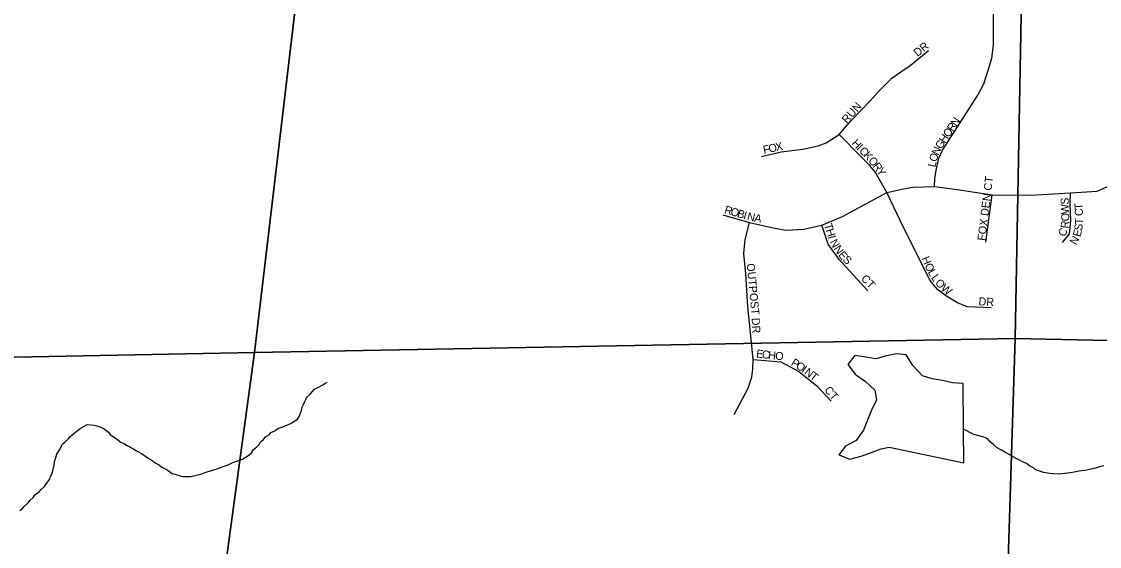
# Model space of a CAD drawing. Extents: x 0 to 34, y -2.3 to 22.
# Drawn here: x 3.123 to 4.399, y 15.2 to 15.821 of the extents above; entities that cross this region are included whole.
import ezdxf

# ---------------------------------------------------------------- set-up
doc = ezdxf.new("R2010")
doc.units = 0
for name, color, linetype in [('GM_X_Minor_River', 7, 'Continuous'), ('GM_X_Section', 7, 'Continuous'), ('GM_X_Township_Subdivision', 7, 'Continuous'), ('GM_X_Township_Subdivision_Text', 7, 'Continuous')]:
    doc.layers.add(name, color=color, linetype=linetype)

msp = doc.modelspace()

# ---------------------------------------------------------------- linework, layer by layer
at = {"layer": 'GM_X_Minor_River'}
for p, q in [((4.1094, 15.4259), (4.1011, 15.4154)), ((4.1223, 15.424), (4.1094, 15.4259)), ((4.1344, 15.4221), (4.1223, 15.424)), ((4.147, 15.4255), (4.1344, 15.4221)), ((4.1585, 15.4282), (4.147, 15.4255)), ((4.1702, 15.4267), (4.1585, 15.4282)), ((4.1782, 15.4143), (4.1702, 15.4267)), ((4.1011, 15.4154), (4.1099, 15.4038)), ((4.1893, 15.4022), (4.1782, 15.4143)), ((4.1099, 15.4038), (4.1218, 15.3954)), ((4.1218, 15.3954), (4.1329, 15.3852)), ((4.201, 15.3985), (4.1893, 15.4022)), ((4.2131, 15.3966), (4.201, 15.3985)), ((4.2251, 15.3939), (4.2131, 15.3966)), ((3.465, 15.3803), (3.4701, 15.3862)), ((3.4701, 15.3862), (3.4739, 15.3884)), ((3.4739, 15.3884), (3.4797, 15.3912)), ((3.4797, 15.3912), (3.4824, 15.393)), ((3.4824, 15.393), (3.4851, 15.3945)), ((4.1329, 15.3852), (4.1349, 15.3738)), ((4.2376, 15.3928), (4.2251, 15.3939)), ((4.238, 15.3391), (4.2376, 15.3928)), ((3.457, 15.368), (3.4582, 15.371)), ((3.4582, 15.371), (3.4598, 15.374)), ((3.4598, 15.374), (3.4611, 15.3766)), ((3.4611, 15.3766), (3.465, 15.3803)), ((4.1349, 15.3738), (4.1292, 15.3614)), ((3.4525, 15.3559), (3.4545, 15.3608)), ((3.4545, 15.3608), (3.4554, 15.365)), ((3.4554, 15.365), (3.457, 15.368)), ((4.1292, 15.3614), (4.1243, 15.3497)), ((3.1982, 15.343), (3.2009, 15.3445)), ((3.2009, 15.3445), (3.2092, 15.3438)), ((3.2092, 15.3438), (3.2126, 15.343)), ((3.4354, 15.3428), (3.4381, 15.3442)), ((3.4381, 15.3442), (3.4419, 15.3456)), ((3.4419, 15.3456), (3.4446, 15.3474)), ((3.4446, 15.3474), (3.45, 15.3507)), ((3.45, 15.3507), (3.4516, 15.3533)), ((3.4516, 15.3533), (3.4525, 15.3559)), ((4.1243, 15.3497), (4.1198, 15.3377)), ((3.1803, 15.3299), (3.1834, 15.3321)), ((3.1834, 15.3321), (3.19, 15.3376)), ((3.19, 15.3376), (3.1928, 15.3398)), ((3.1928, 15.3398), (3.1982, 15.343)), ((3.2126, 15.343), (3.216, 15.3417)), ((3.216, 15.3417), (3.2201, 15.3401)), ((3.2201, 15.3401), (3.2261, 15.3353)), ((3.2261, 15.3353), (3.2283, 15.3326)), ((3.2283, 15.3326), (3.2369, 15.3267)), ((3.4122, 15.3298), (3.4164, 15.3323)), ((3.4164, 15.3323), (3.4184, 15.3349)), ((3.4184, 15.3349), (3.4238, 15.3374)), ((3.4238, 15.3374), (3.4265, 15.3396)), ((3.4265, 15.3396), (3.4327, 15.3417)), ((3.4327, 15.3417), (3.4354, 15.3428)), ((4.1198, 15.3377), (4.111, 15.3254)), ((4.2383, 15.2992), (4.238, 15.3391)), ((4.2493, 15.3329), (4.238, 15.3391)), ((4.2519, 15.3321), (4.2493, 15.3329)), ((4.261, 15.3299), (4.2519, 15.3321)), ((3.1681, 15.3143), (3.1717, 15.321)), ((3.1717, 15.321), (3.1748, 15.324)), ((3.1748, 15.324), (3.1787, 15.3269)), ((3.1787, 15.3269), (3.1803, 15.3299)), ((3.2369, 15.3267), (3.2402, 15.3239)), ((3.2402, 15.3239), (3.2451, 15.3215)), ((3.2451, 15.3215), (3.2484, 15.3195)), ((3.2484, 15.3195), (3.2552, 15.3162)), ((3.4016, 15.318), (3.4047, 15.3209)), ((3.4047, 15.3209), (3.4063, 15.3239)), ((3.4063, 15.3239), (3.4094, 15.3261)), ((3.4094, 15.3261), (3.4122, 15.3298)), ((4.0983, 15.3189), (4.0904, 15.3085)), ((4.111, 15.3254), (4.0983, 15.3189)), ((4.2647, 15.3283), (4.261, 15.3299)), ((4.2673, 15.3267), (4.2647, 15.3283)), ((4.2695, 15.324), (4.2673, 15.3267)), ((4.274, 15.3204), (4.2695, 15.324)), ((4.2777, 15.3169), (4.274, 15.3204)), ((3.1624, 15.3004), (3.1644, 15.3064)), ((3.1644, 15.3064), (3.1653, 15.3094)), ((3.1653, 15.3094), (3.1681, 15.3143)), ((3.2552, 15.3162), (3.2593, 15.3131)), ((3.2593, 15.3131), (3.266, 15.3098)), ((3.266, 15.3098), (3.2705, 15.3067)), ((3.2705, 15.3067), (3.2731, 15.3047)), ((3.3848, 15.3036), (3.3891, 15.3062)), ((3.3891, 15.3062), (3.3922, 15.308)), ((3.3922, 15.308), (3.3953, 15.3109)), ((3.3953, 15.3109), (3.3977, 15.315)), ((3.3977, 15.315), (3.4016, 15.318)), ((4.0904, 15.3085), (4.1036, 15.3036)), ((4.1036, 15.3036), (4.117, 15.307)), ((4.117, 15.307), (4.1266, 15.3105)), ((4.1266, 15.3105), (4.1404, 15.3158)), ((4.1404, 15.3158), (4.15, 15.3178)), ((4.15, 15.3178), (4.2383, 15.2992)), ((4.2822, 15.3145), (4.2777, 15.3169)), ((4.2867, 15.3117), (4.2822, 15.3145)), ((4.2919, 15.3089), (4.2867, 15.3117)), ((4.2945, 15.3073), (4.2919, 15.3089)), ((4.3043, 15.3024), (4.2945, 15.3073)), ((3.1602, 15.2898), (3.1619, 15.2962)), ((3.1619, 15.2962), (3.1624, 15.3004)), ((3.2731, 15.3047), (3.2776, 15.3023)), ((3.2776, 15.3023), (3.2813, 15.2991)), ((3.2813, 15.2991), (3.2865, 15.2963)), ((3.2865, 15.2963), (3.2895, 15.2939)), ((3.2895, 15.2939), (3.2955, 15.2907)), ((3.3537, 15.2917), (3.3621, 15.2948)), ((3.3621, 15.2948), (3.3679, 15.2969)), ((3.3679, 15.2969), (3.3725, 15.2991)), ((3.3725, 15.2991), (3.3764, 15.3005)), ((3.3764, 15.3005), (3.3848, 15.3036)), ((4.3069, 15.3008), (4.3043, 15.3024)), ((4.3125, 15.2984), (4.3069, 15.3008)), ((4.3159, 15.2956), (4.3125, 15.2984)), ((4.3207, 15.2932), (4.3159, 15.2956)), ((4.3233, 15.2908), (4.3207, 15.2932)), ((4.3941, 15.2929), (4.3849, 15.2909)), ((4.3987, 15.2943), (4.3941, 15.2929)), ((4.404, 15.2956), (4.3987, 15.2943)), ((3.1568, 15.2797), (3.1577, 15.2831)), ((3.1577, 15.2831), (3.1593, 15.2857)), ((3.1593, 15.2857), (3.1602, 15.2898)), ((3.2955, 15.2907), (3.3015, 15.2864)), ((3.3015, 15.2864), (3.3049, 15.2855)), ((3.3049, 15.2855), (3.3124, 15.2834)), ((3.3124, 15.2834), (3.315, 15.2829)), ((3.315, 15.2829), (3.3207, 15.2828)), ((3.3207, 15.2828), (3.3238, 15.283)), ((3.3238, 15.283), (3.3356, 15.2857)), ((3.3356, 15.2857), (3.3395, 15.2871)), ((3.3395, 15.2871), (3.3506, 15.2906)), ((3.3506, 15.2906), (3.3537, 15.2917)), ((4.3293, 15.2887), (4.3233, 15.2908)), ((4.3327, 15.2875), (4.3293, 15.2887)), ((4.3399, 15.2865), (4.3327, 15.2875)), ((4.3437, 15.286), (4.3399, 15.2865)), ((4.3517, 15.2858), (4.3437, 15.286)), ((4.3544, 15.2861), (4.3517, 15.2858)), ((4.3647, 15.2873), (4.3544, 15.2861)), ((4.3689, 15.2879), (4.3647, 15.2873)), ((4.375, 15.2893), (4.3689, 15.2879)), ((4.3815, 15.2902), (4.375, 15.2893)), ((4.3849, 15.2909), (4.3815, 15.2902)), ((3.1438, 15.2645), (3.1466, 15.2674)), ((3.1466, 15.2674), (3.1505, 15.2711)), ((3.1505, 15.2711), (3.1529, 15.2745)), ((3.1529, 15.2745), (3.1568, 15.2797)), ((3.1313, 15.2516), (3.1333, 15.2545)), ((3.1333, 15.2545), (3.1372, 15.2582)), ((3.1372, 15.2582), (3.1396, 15.2616)), ((3.1396, 15.2616), (3.1438, 15.2645)), ((3.1212, 15.2427), (3.1246, 15.2449)), ((3.1246, 15.2449), (3.1266, 15.2475)), ((3.1266, 15.2475), (3.1313, 15.2516))]:
    msp.add_line(p, q, dxfattribs=at)
at = {"layer": 'GM_X_Section'}
for p, q in [((3.5141, 16.4057), (3.3991, 15.4295)), ((3.3991, 15.4295), (3.5141, 16.4057)), ((4.317, 16.3953), (4.2992, 15.4463)), ((4.2992, 15.4463), (4.317, 16.3953)), ((4.2992, 15.4463), (3.3991, 15.4295)), ((3.3991, 15.4295), (4.2992, 15.4463)), ((4.268, 14.4527), (4.2992, 15.4463)), ((4.2992, 15.4463), (4.268, 14.4527)), ((5.3014, 15.4224), (4.2992, 15.4463)), ((4.2992, 15.4463), (5.3014, 15.4224)), ((3.3991, 15.4295), (2.4872, 15.4126)), ((2.4872, 15.4126), (3.3991, 15.4295)), ((3.2685, 14.4772), (3.3991, 15.4295)), ((3.3991, 15.4295), (3.2685, 14.4772))]:
    msp.add_line(p, q, dxfattribs=at)
at = {"layer": 'GM_X_Township_Subdivision'}
for p, q in [((4.2733, 15.8147), (4.2733, 15.8348)), ((4.2733, 15.7932), (4.2733, 15.8147)), ((4.2714, 15.7779), (4.2733, 15.7932)), ((4.1749, 15.7692), (4.1967, 15.7869)), ((4.2677, 15.7649), (4.2714, 15.7779)), ((4.1639, 15.7617), (4.1749, 15.7692)), ((4.2621, 15.7474), (4.2677, 15.7649)), ((4.1453, 15.7463), (4.1532, 15.7541)), ((4.1532, 15.7541), (4.1639, 15.7617)), ((4.1372, 15.7385), (4.1453, 15.7463)), ((4.2551, 15.734), (4.2621, 15.7474)), ((4.1053, 15.7045), (4.1279, 15.7277)), ((4.1279, 15.7277), (4.1372, 15.7385)), ((4.2132, 15.669), (4.2551, 15.734)), ((4.0907, 15.6876), (4.1053, 15.7045)), ((4.0658, 15.6741), (4.0756, 15.6778)), ((4.0756, 15.6778), (4.0907, 15.6876)), ((4.1174, 15.6606), (4.0907, 15.6876)), ((3.9991, 15.6617), (4.0222, 15.667)), ((4.0222, 15.667), (4.0478, 15.6702)), ((4.0478, 15.6702), (4.0658, 15.6741)), ((4.2089, 15.6594), (4.2132, 15.669)), ((4.127, 15.6508), (4.1174, 15.6606)), ((4.1337, 15.6424), (4.127, 15.6508)), ((4.2058, 15.6452), (4.2089, 15.6594)), ((4.1395, 15.6328), (4.1337, 15.6424)), ((4.204, 15.6352), (4.2058, 15.6452)), ((4.3961, 15.6205), (4.4346, 15.6378)), ((4.1471, 15.6188), (4.1395, 15.6328)), ((4.1671, 15.6232), (4.1782, 15.6252)), ((4.1782, 15.6252), (4.2035, 15.626)), ((4.2035, 15.626), (4.204, 15.6352)), ((4.2035, 15.626), (4.2303, 15.6223)), ((4.0947, 15.5906), (4.1471, 15.6188)), ((4.1471, 15.6188), (4.1671, 15.6232)), ((4.1633, 15.5852), (4.1471, 15.6188)), ((4.2303, 15.6223), (4.2718, 15.6162)), ((4.2643, 15.5602), (4.2718, 15.6162)), ((4.2718, 15.6162), (4.3175, 15.6158)), ((4.3175, 15.6158), (4.3644, 15.6184)), ((4.3641, 15.6062), (4.3644, 15.6184)), ((4.3644, 15.6184), (4.3961, 15.6205)), ((4.3651, 15.5853), (4.3641, 15.6062)), ((3.9531, 15.5924), (3.9849, 15.5836)), ((4.0704, 15.5802), (4.0947, 15.5906)), ((3.9795, 15.5634), (3.9849, 15.5836)), ((3.9849, 15.5836), (4.0129, 15.577)), ((4.0129, 15.577), (4.0283, 15.5744)), ((4.0283, 15.5744), (4.0489, 15.5756)), ((4.0489, 15.5756), (4.0704, 15.5802)), ((4.078, 15.5579), (4.0704, 15.5802)), ((4.1897, 15.5317), (4.1633, 15.5852)), ((4.3634, 15.5701), (4.3651, 15.5853)), ((3.9781, 15.5468), (3.9795, 15.5634)), ((4.3552, 15.5597), (4.3634, 15.5701)), ((4.0907, 15.5396), (4.078, 15.5579)), ((3.9804, 15.5227), (3.9781, 15.5468)), ((4.1248, 15.5027), (4.0907, 15.5396)), ((3.9827, 15.4835), (3.9804, 15.5227)), ((4.1987, 15.5149), (4.1897, 15.5317)), ((4.2072, 15.5042), (4.1987, 15.5149)), ((4.2182, 15.4957), (4.2072, 15.5042)), ((4.231, 15.4882), (4.2182, 15.4957)), ((4.2423, 15.4838), (4.231, 15.4882)), ((3.9859, 15.4533), (3.9827, 15.4835)), ((4.2707, 15.4824), (4.2423, 15.4838)), ((3.9891, 15.4214), (3.9859, 15.4533)), ((3.9888, 15.4104), (3.9891, 15.4214)), ((3.9891, 15.4214), (4.022, 15.4185)), ((3.9874, 15.4005), (3.9888, 15.4104)), ((4.022, 15.4185), (4.0433, 15.4073)), ((3.9833, 15.3874), (3.9874, 15.4005)), ((4.0433, 15.4073), (4.0642, 15.3907)), ((3.9665, 15.3564), (3.9833, 15.3874)), ((4.0642, 15.3907), (4.0812, 15.3721))]:
    msp.add_line(p, q, dxfattribs=at)

# ---------------------------------------------------------------- texts
at = {"layer": 'GM_X_Township_Subdivision_Text'}
for s, rotation, p in [('DR', 38.1565, (4.1835, 15.7792)), ('RUN', 48.1233, (4.1, 15.6999)), ('R', 56.0018, (4.2254, 15.6902)), ('N', 56.0018, (4.2296, 15.6964)), ('H', 56.0144, (4.216, 15.6764)), ('O', 56.0053, (4.2207, 15.6833)), ('F', 11.8324, (4.0018, 15.6646)), ('O', 11.8318, (4.0083, 15.666)), ('X', 12.5173, (4.0166, 15.6677)), ('H', 313.7673, (4.1051, 15.6766)), ('I', 313.7483, (4.1108, 15.6706)), ('G', 57.3587, (4.2116, 15.6694)), ('C', 313.7663, (4.1137, 15.6676)), ('K', 313.7673, (4.1189, 15.6621)), ('O', 73.7634, (4.206, 15.6545)), ('N', 65.0088, (4.2082, 15.6622)), ('O', 311.447, (4.1246, 15.6562)), ('R', 306.2943, (4.13, 15.6501)), ('L', 76.9644, (4.2046, 15.6482)), ('Y', 303.4279, (4.1344, 15.6442)), ('FOX DEN CT', 82.9618, (4.2637, 15.5614)), ('S', 88.0326, (4.3623, 15.6043)), ('R', 343.5025, (3.9543, 15.5945)), ('O', 343.4926, (3.9615, 15.5924)), ('B', 343.4977, (3.9695, 15.5901)), ('W', 93.7649, (4.363, 15.5937)), ('T', 92.8017, (4.379, 15.5988)), ('C', 94.1356, (4.3795, 15.5914)), ('I', 343.5117, (3.9767, 15.5879)), ('N', 346.7533, (3.9813, 15.5866)), ('A', 349.9328, (3.9899, 15.5846)), ('O', 91.0971, (4.3632, 15.5849)), ('T', 87.0526, (4.3793, 15.5809)), ('T', 286.7176, (4.073, 15.5808)), ('H', 286.7217, (4.0749, 15.5745)), ('C', 62.2347, (4.3575, 15.5658)), ('R', 82.6307, (4.3621, 15.576)), ('E', 75.2954, (4.3762, 15.5658)), ('S', 80.9052, (4.3781, 15.5732)), ('I', 286.7165, (4.0773, 15.5665)), ('N', 298.6302, (4.0794, 15.5605)), ('N', 60.6285, (4.3712, 15.5561)), ('N', 304.6385, (4.0839, 15.5523)), ('E', 308.8792, (4.0891, 15.5448)), ('S', 316.7636, (4.0943, 15.5386)), ('H', 292.7014, (4.188, 15.541)), ('O', 296.6582, (4.1915, 15.5326)), ('OUTPOST', 275.4414, (3.9814, 15.5346)), ('L', 298.8858, (4.1954, 15.5248)), ('L', 303.7429, (4.1991, 15.5182)), ('CT', 312.7085, (4.116, 15.5165)), ('O', 311.5519, (4.2037, 15.5116)), ('W', 321.0905, (4.2104, 15.5042)), ('DR', 356.9889, (4.2556, 15.4855)), ('DR', 273.011, (3.9873, 15.4704)), ('E', 353.7171, (3.9923, 15.4238)), ('C', 353.7094, (3.999, 15.423)), ('H', 353.7116, (4.0064, 15.4222)), ('O', 354.4425, (4.0148, 15.4213)), ('P', 328.2386, (4.0331, 15.4152)), ('O', 326.5494, (4.0387, 15.4117)), ('I', 323.2656, (4.0455, 15.4072)), ('N', 322.5793, (4.0488, 15.4047)), ('T', 322.5372, (4.0554, 15.3997)), ('CT', 310.6016, (4.0727, 15.3848))]:
    msp.add_text(s, height=0.00947, rotation=rotation, dxfattribs=at).set_placement(p)

doc.saveas('drawing.dxf')
